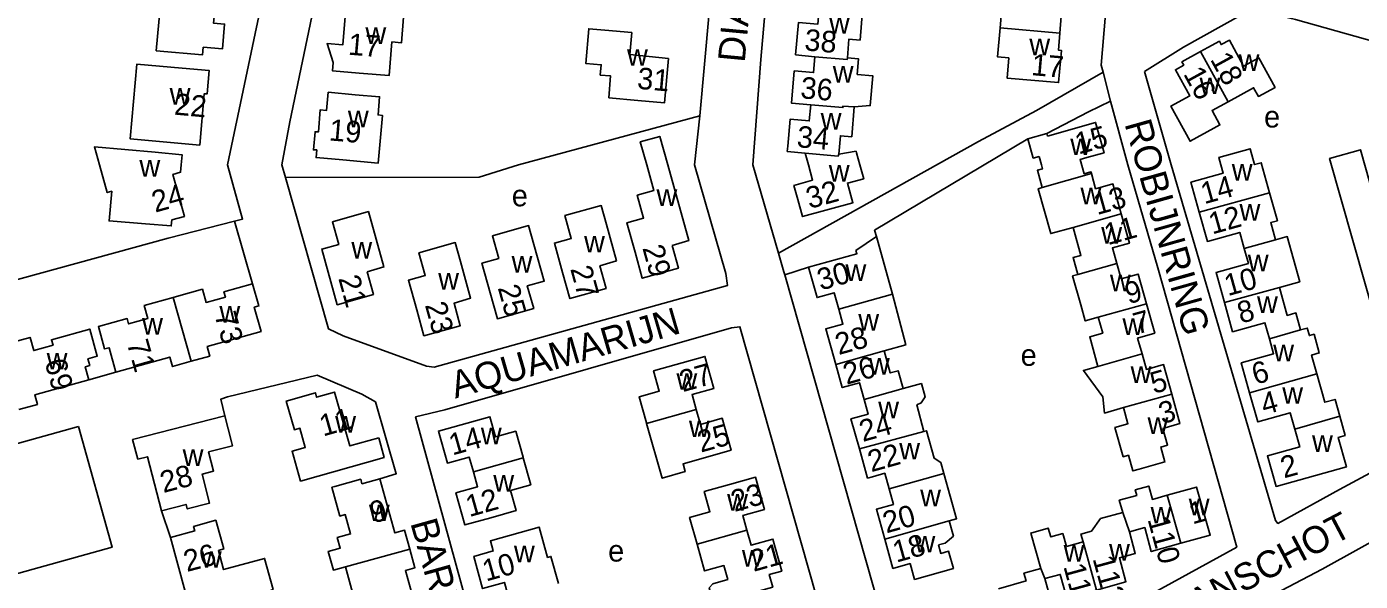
# Model space of a CAD drawing. Extents: x 159441 to 162086, y 388175 to 389787.
# Drawn here: x 159843.1 to 160090.5, y 388422.7 to 388525.7 of the extents above; entities that cross this region are included whole.
import ezdxf

# ---------------------------------------------------------------- set-up
doc = ezdxf.new("R2010")
doc.units = 0
for name, color, linetype in [('BLT_Basislijn', 7, 'Continuous'), ('BLT_Bebouwing', 7, 'Continuous'), ('BLT_Centroide', 7, 'Continuous'), ('BLT_Huisnummer', 7, 'Continuous'), ('BLT_Huisnummer_ tussenligend', 7, 'Continuous'), ('BLT_Onderverdeling_panden', 7, 'Continuous'), ('BLT_Straatnaam', 7, 'Continuous')]:
    doc.layers.add(name, color=color, linetype=linetype)

msp = doc.modelspace()

# ---------------------------------------------------------------- linework, layer by layer
at = {"layer": 'BLT_Basislijn'}
for p, q in [((160042.82, 388517.23), (160044.18, 388511.83)), ((159884.99, 388477.96), (159881.64, 388489.55)), ((159988.12, 388481.03), (159983.72, 388479.59)), ((159859.61, 388461.57), (159854.59, 388460.15)), ((159868.09, 388435.82), (159869.73, 388430.84))]:
    msp.add_line(p, q, dxfattribs=at)
for points in [[(159891.07, 388497.69), (159890.41, 388500), (159891.9, 388508.03), (159910.92, 388599.34), (159955.29, 388634.61), (159956.63, 388635.6), (159957.4, 388635.69), (159960.58, 388634.48), (159981.08, 388624.35), (159997.24, 388603.77)], [(159881.64, 388489.55), (159883.13, 388489.92), (159880.31, 388500), (159901.75, 388601.71), (159904.27, 388615.04)], [(159997.24, 388603.77), (159976.03, 388587.11), (159974.89, 388585.92), (159967.94, 388509.11)], [(160007.91, 388598.99), (159987, 388582.82), (159984.23, 388575.97), (159979.27, 388519.56), (159977.78, 388500), (159982.53, 388483.63)], [(160042.82, 388517.23), (160042.45, 388518.56), (160045.07, 388549.89), (160045.32, 388550.52), (160046.02, 388551.08)], [(160069.29, 388528.74), (160068.45, 388527.87), (160057.7, 388521.87), (160050.49, 388517.35)], [(160119.41, 388515.48), (160078.46, 388526.99), (160070.12, 388528.98), (160069.29, 388528.74)], [(160042.82, 388517.23), (160030.41, 388510.14), (160019.67, 388504.39), (159982.53, 388483.63)], [(160100.2, 388447.07), (160086.64, 388439.75), (160075.23, 388433.46), (160074.75, 388434.01), (160055.42, 388500), (160050.49, 388517.35)], [(160044.18, 388511.83), (160047.34, 388500), (160052.91, 388480.91), (160067.59, 388429.07), (160008.55, 388396.67), (160007.63, 388396.55), (160006.91, 388397.91), (159983.72, 388479.59)], [(160044.18, 388511.83), (160040.05, 388509.89), (160032.33, 388505.82)], [(159891.07, 388497.69), (159926.99, 388497.75), (159934.29, 388500), (159967.94, 388509.11)], [(159967.94, 388509.11), (159966.98, 388500), (159972.81, 388479.85), (159973.11, 388477.66), (159918.64, 388462.48), (159917.27, 388462.67), (159901.76, 388468.27), (159899.06, 388469.61), (159891.07, 388497.69)], [(160028.82, 388504.83), (160000.39, 388487.88), (160000.71, 388486.74)], [(160105.46, 388450.09), (160090.56, 388502.82), (160084.8, 388501.19), (160100.2, 388447.07)], [(159824.86, 388474.25), (159869.34, 388486.43), (159881.64, 388489.55)], [(159982.53, 388483.63), (159983.56, 388480.15), (159983.72, 388479.59)], [(159934.85, 388382.82), (159925.9, 388414.21), (159915.23, 388453.23), (159920.65, 388454.53), (159973.85, 388469.77), (159975.39, 388469.98), (159995.27, 388399.83)], [(159908.61, 388441.76), (159911.63, 388442.69), (159907.81, 388456.01), (159905.27, 388457.45), (159896.95, 388460.98), (159880.33, 388456.97), (159879.06, 388456.51), (159879.84, 388453.47)], [(160073.38, 388419.71), (160083.44, 388425.01), (160135.09, 388453.64), (160136.7, 388454.22), (160149.05, 388411.9), (160149.19, 388410.5), (160082.23, 388391.17), (160081.75, 388391.93), (160078.89, 388400.97)], [(159852.68, 388451.49), (159858.93, 388429.04), (159832.88, 388421.82), (159829.18, 388423.91), (159824.59, 388440.25), (159826.87, 388444.28), (159852.68, 388451.49)]]:
    msp.add_lwpolyline(points, dxfattribs=at)
at = {"layer": 'BLT_Bebouwing'}
for p, q in [((160032.33, 388505.82), (160028.82, 388504.83)), ((160032.45, 388505.38), (160032.33, 388505.82))]:
    msp.add_line(p, q, dxfattribs=at)
for points in [[(159876.25, 388533.66), (159862.92, 388534.88), (159862.46, 388529.7), (159867.84, 388529.2), (159867.1, 388521.21), (159875.66, 388520.42), (159875.82, 388521.85), (159879.38, 388521.56), (159879.79, 388526.14), (159877.73, 388526.32), (159877.89, 388528.12), (159878.65, 388528.05), (159878.74, 388529.05), (159880.84, 388528.87), (159881.23, 388533.21), (159876.25, 388533.66)], [(160023.66, 388525.43), (160024.12, 388530.66), (160026.22, 388530.48), (160026.52, 388533.95)], [(160032.53, 388533.85), (160036.12, 388533.54), (160035.6, 388527.56), (160035.03, 388527.61), (160034.76, 388524.47)], [(159907.22, 388527.89), (159902.24, 388528.29), (159901.71, 388522.28), (159898.8, 388522.54), (159899.91, 388519.02), (159899.8, 388517.48), (159904.78, 388517.06), (159910.3, 388516.6), (159910.82, 388522.85), (159912.61, 388522.7), (159913, 388527.43), (159907.22, 388527.89)], [(159989.31, 388520.09), (159985.73, 388520.46), (159986.25, 388526.43), (159989.83, 388526.12), (159990.08, 388529.04)], [(159995.33, 388519.91), (159995.6, 388523.35), (159997.69, 388523.17), (159998.17, 388528.7), (159996.13, 388528.88)], [(159951.05, 388512.46), (159956.43, 388511.99), (159961.41, 388511.56), (159962.12, 388519.76), (159954.95, 388520.52), (159955.33, 388524.59), (159950.35, 388525.02), (159947.34, 388525.28), (159946.78, 388518.86), (159949.66, 388518.61), (159949.49, 388516.7), (159951.4, 388516.53), (159951.05, 388512.46)], [(160034.76, 388524.47), (160034.48, 388521.32), (160035.05, 388521.27), (160034.53, 388515.29), (160024.96, 388516.12), (160025.29, 388519.88), (160023.2, 388520.06), (160023.66, 388525.43)], [(160060.88, 388521.05), (160062.22, 388521.79), (160064.35, 388522.96), (160064.68, 388522.34), (160066.21, 388523.18), (160068.85, 388518.34), (160071.69, 388519.89), (160074.69, 388514.41), (160071.6, 388512.72), (160070.71, 388514.34), (160065.99, 388511.75)], [(159988.53, 388511.14), (159984.95, 388511.49), (159985.47, 388517.47), (159989.05, 388517.16), (159989.31, 388520.09)], [(159997.13, 388516.78), (159997.39, 388519.73), (159995.33, 388519.91)], [(160065.99, 388511.75), (160062.99, 388510.12), (160064.45, 388507.45), (160063.3, 388506.82), (160058.92, 388504.42), (160055.36, 388510.92), (160058.87, 388512.83), (160056.21, 388517.69), (160057.74, 388518.53), (160057.4, 388519.14), (160060.88, 388521.05)], [(159875.18, 388503.67), (159876.02, 388513.23), (159876.52, 388513.19), (159876.92, 388517.56), (159871.94, 388518), (159863.52, 388518.74), (159862.28, 388504.83), (159875.18, 388503.67)], [(159996.61, 388510.77), (159999.59, 388511.02), (160000.07, 388516.52), (159997.13, 388516.78)], [(159903.99, 388513.05), (159908.55, 388512.66), (159908.26, 388509.28), (159909.05, 388509.21), (159908.28, 388500.35), (159901.74, 388500.93), (159896.76, 388501.38), (159896.87, 388502.79), (159896.27, 388502.81), (159896.56, 388506.18), (159897.18, 388506.13), (159897.53, 388510.24), (159898.72, 388510.13), (159899.01, 388513.49), (159903.99, 388513.05)], [(159987.51, 388502.17), (159984.17, 388502.51), (159984.26, 388503.52), (159984.69, 388508.5), (159988.27, 388508.19), (159988.53, 388511.14)], [(159993.74, 388501.98), (159994.04, 388505.42), (159996.13, 388505.24), (159996.61, 388510.77)], [(160032.45, 388505.38), (160041.4, 388507.89), (160042.97, 388502.27), (160039.78, 388501.37), (160038.52, 388501.02), (160039.26, 388498.38), (160040.52, 388498.74), (160040.6, 388498.44)], [(159962.85, 388485.08), (159965.94, 388485.98), (159962.02, 388500), (159960.53, 388505.32), (159956.9, 388504.3), (159958.1, 388500), (159959.43, 388495.25), (159956.35, 388494.39), (159957.53, 388490.14), (159954.4, 388489.27), (159955.93, 388483.8), (159957.27, 388478.98), (159963.99, 388480.87), (159962.85, 388485.08)], [(160028.82, 388504.83), (160029.82, 388501.27), (160030.91, 388501.58)], [(159866.92, 388502.36), (159871.9, 388501.91), (159871.74, 388500), (159871.62, 388498.66), (159870.15, 388498.26), (159872.32, 388490.46), (159870, 388489.81), (159869.89, 388488.7), (159865.08, 388489.09), (159858.35, 388489.62), (159858.85, 388495.12), (159858.01, 388494.89), (159856.58, 388500), (159855.64, 388503.38), (159866.92, 388502.36)], [(159993.74, 388501.98), (159996.96, 388502.55), (159997.04, 388502.28), (159997.67, 388500), (159998.37, 388497.46), (159995.35, 388496.63), (159996.35, 388493), (159987.02, 388490.42), (159986.14, 388493.61), (159985.42, 388496.22), (159988.89, 388497.18), (159988.11, 388500), (159987.51, 388502.17)], [(160060.62, 388491.24), (160059.07, 388496.8), (160065.06, 388498.47), (160064.64, 388500), (160064.25, 388501.4), (160070.07, 388503.02), (160070.88, 388500.09), (160072.12, 388500.43), (160073.68, 388494.81)], [(160031.49, 388495.81), (160030.58, 388499.04), (160031.54, 388499.31), (160031.35, 388500), (160030.91, 388501.58)], [(160040.6, 388498.44), (160041.4, 388495.59), (160044.59, 388496.48), (160046.15, 388490.93)], [(160037.2, 388488.42), (160033.06, 388487.26), (160030.72, 388495.59), (160031.49, 388495.81)], [(160073.68, 388494.81), (160075.12, 388489.64), (160073.88, 388489.3), (160074.77, 388486.11)], [(159950.64, 388488.98), (159952.49, 388482.21), (159949.41, 388481.26), (159950.56, 388477.08), (159943.84, 388475.22), (159942.5, 388480.04), (159940.99, 388485.51), (159944.11, 388486.38), (159942.93, 388490.61), (159949.67, 388492.48), (159950.64, 388488.98)], [(159906.24, 388480.19), (159907.4, 388475.98), (159900.69, 388474.07), (159897.82, 388484.39), (159900.95, 388485.22), (159899.78, 388489.47), (159906.46, 388491.34), (159909.35, 388481.09), (159906.24, 388480.19)], [(160046.15, 388490.93), (160047.67, 388485.5), (160044.51, 388484.6), (160045.32, 388481.73)], [(160068.96, 388484.48), (160068.12, 388487.48), (160062.13, 388485.81), (160060.62, 388491.24)], [(159937.18, 388485.23), (159939.1, 388478.44), (159935.95, 388477.56), (159937.13, 388473.34), (159930.4, 388471.46), (159929.06, 388476.27), (159927.52, 388481.76), (159930.65, 388482.63), (159929.47, 388486.87), (159936.2, 388488.75), (159937.18, 388485.23)], [(160037.2, 388488.42), (160038.66, 388483.22), (160037.2, 388482.81), (160038.08, 388479.67)], [(159923.57, 388482.06), (159925.43, 388475.3), (159922.35, 388474.35), (159923.5, 388470.16), (159916.77, 388468.3), (159915.43, 388473.12), (159913.89, 388478.62), (159917.02, 388479.5), (159915.84, 388483.72), (159922.58, 388485.6), (159923.57, 388482.06)], [(159988.12, 388481.03), (159997.09, 388483.54), (159996.93, 388484.1), (160000.71, 388486.74)], [(160000.71, 388486.74), (160003.7, 388476.01)], [(160074.77, 388486.11), (160076.94, 388486.72), (160079.27, 388478.34), (160075.51, 388477.29)], [(160065.3, 388474.45), (160063.74, 388480.04), (160069.73, 388481.71), (160068.96, 388484.48)], [(159993.74, 388473.23), (159992.89, 388476.28), (159989.71, 388475.39), (159988.12, 388481.03)], [(160045.32, 388481.73), (160046.15, 388478.84), (160049.31, 388479.74), (160050.83, 388474.25)], [(159884.99, 388477.96), (159879.66, 388476.48), (159879.93, 388475.49), (159876.34, 388474.49), (159875.66, 388476.94), (159870.85, 388475.6), (159870.22, 388475.43)], [(159884.99, 388477.96), (159886.14, 388473.83), (159885.3, 388473.6), (159886.56, 388469.07), (159876.55, 388466.29), (159877.04, 388464.54), (159873.58, 388463.56)], [(160038.08, 388479.67), (160037.12, 388479.4), (160038.62, 388474.05), (160039.46, 388471.05), (160041.87, 388471.75)], [(160075.51, 388477.29), (160076.96, 388472.09), (160078.55, 388472.54), (160079.43, 388469.38)], [(159859.61, 388461.57), (159858.36, 388466.09), (159857.52, 388465.86), (159856.37, 388470), (159861.71, 388471.48), (159861.98, 388470.5), (159865.55, 388471.49), (159864.87, 388473.94), (159870.22, 388475.43)], [(160003.7, 388476.01), (160006.16, 388466.61), (160002.14, 388465.51)], [(159993.17, 388462.99), (159991.32, 388469.59), (159994.52, 388470.48), (159993.74, 388473.23)], [(160050.83, 388474.25), (160052.36, 388468.76), (160049.18, 388467.87), (160050, 388464.95)], [(160073.64, 388467.74), (160072.8, 388470.73), (160066.8, 388469.06), (160065.3, 388474.45)], [(160041.87, 388471.75), (160042.71, 388468.76), (160040.29, 388468.08), (160041.82, 388462.62)], [(159838.23, 388466.48), (159843.68, 388468.01), (159844.37, 388465.56), (159847.95, 388466.56), (159847.66, 388467.57), (159854.76, 388469.55), (159856.16, 388464.53), (159854.41, 388464.04), (159854.76, 388462.79), (159853.92, 388462.55), (159854.59, 388460.15)], [(160069.97, 388457.73), (160068.42, 388463.29), (160074.41, 388464.96), (160073.64, 388467.74)], [(160079.43, 388469.38), (160080.67, 388469.73), (160081.07, 388468.33), (160081.93, 388468.57), (160082.9, 388465.11), (160081.45, 388464.71), (160082.45, 388461.22)], [(160002.14, 388465.51), (160003.29, 388461.4), (160004.74, 388461.81), (160005.68, 388458.49)], [(160050, 388464.95), (160050.81, 388462.07), (160053.99, 388462.96), (160055.52, 388457.49)], [(159873.58, 388463.56), (159870.12, 388462.58), (159869.62, 388464.36), (159859.61, 388461.57)], [(159967.3, 388454.62), (159966.52, 388457.38), (159970.56, 388458.51), (159968.9, 388464.46), (159959.37, 388461.78), (159960.43, 388458.03), (159956.68, 388456.97), (159958.04, 388452.16), (159958.07, 388452.04)], [(159998.44, 388456.47), (159997.57, 388459.57), (159994.38, 388458.68), (159993.17, 388462.99)], [(160041.82, 388462.62), (160039.12, 388461.87), (160042.72, 388456.95), (160043.07, 388453.95), (160046.55, 388454.99)], [(159854.59, 388460.15), (159844.57, 388457.34), (159845.06, 388455.57), (159841.6, 388454.59)], [(160082.45, 388461.22), (160083.91, 388455.97), (160085.83, 388456.5), (160086.7, 388453.38)], [(159908.37, 388449.35), (159909.38, 388445.72), (159893.88, 388441.33), (159892.3, 388446.88), (159894.76, 388447.58), (159893.75, 388451.14), (159892.74, 388450.85), (159891.23, 388456.19), (159896.62, 388457.72), (159896.85, 388456.89), (159900.2, 388457.84), (159903.02, 388447.87), (159908.37, 388449.35)], [(160005.68, 388458.49), (160009.07, 388459.43), (160009.76, 388456.98), (160009.03, 388455.85), (160008.23, 388455.49), (160009.55, 388450.53)], [(160046.55, 388454.99), (160047.4, 388451.98), (160044.98, 388451.3), (160046.51, 388445.86), (160047.47, 388446.13), (160048.29, 388443.21), (160049.45, 388443.54), (160054.26, 388444.89), (160053.49, 388447.63), (160054.76, 388447.99), (160053.88, 388451.12), (160057.04, 388452.01), (160055.52, 388457.49)], [(160078.34, 388450.99), (160077.49, 388454), (160071.48, 388452.31), (160069.97, 388457.73)], [(159997.56, 388447.32), (159996, 388452.88), (159999.19, 388453.77), (159998.44, 388456.47)], [(159879.84, 388453.47), (159862.72, 388449.03), (159863.71, 388445.4), (159865.49, 388445.86), (159868.09, 388435.82)], [(159868.09, 388435.82), (159872.63, 388437), (159872.85, 388436.17), (159876.99, 388437.24), (159875.6, 388442.61), (159877.74, 388443.16), (159876.81, 388446.74), (159881.28, 388447.9), (159881.09, 388448.63), (159879.84, 388453.47)], [(159935.2, 388445.65), (159935.16, 388445.78), (159933.81, 388450.59), (159930.05, 388449.54), (159929.01, 388453.28), (159919.46, 388450.61), (159921.13, 388444.66), (159925.16, 388445.8), (159925.94, 388443.03)], [(159958.07, 388452.04), (159960.99, 388441.87), (159965.25, 388443.08), (159964.84, 388444.53), (159973.77, 388447.05), (159972.11, 388453), (159968.07, 388451.86), (159967.3, 388454.62)], [(160086.7, 388453.38), (160087.69, 388449.81), (160086.39, 388449.45), (160087.92, 388443.96), (160074.87, 388440.33), (160073.28, 388445.99), (160079.27, 388447.67), (160078.34, 388450.99)], [(160009.55, 388450.53), (160009.99, 388450.66), (160011.41, 388445.57), (160012.69, 388444.76), (160013.26, 388442.73)], [(159925.94, 388443.03), (159926.72, 388440.27), (159922.69, 388439.13), (159924.36, 388433.18), (159929.18, 388434.53), (159933.9, 388435.85), (159932.85, 388439.6), (159936.6, 388440.65), (159935.2, 388445.65)], [(160003.08, 388439.88), (160002.27, 388442.78), (160000, 388442.15), (159999.08, 388441.89), (159997.56, 388447.32)], [(160013.26, 388442.73), (160015.61, 388434.34), (160014.23, 388433.95)], [(159902.19, 388425.42), (159899.96, 388424.8), (159898.99, 388428.29), (159901.23, 388428.9), (159900.69, 388430.84), (159903.16, 388431.52), (159902.17, 388435.1), (159901.17, 388434.82), (159899.68, 388440.2), (159900.21, 388440.35), (159905.03, 388441.68), (159905.26, 388440.84), (159908.61, 388441.76)], [(159914.14, 388428.71), (159913.17, 388432.19), (159911.39, 388431.7), (159908.61, 388441.76)], [(159976.69, 388432.19), (159975.91, 388434.95), (159979.95, 388436.08), (159978.29, 388442.03), (159973.48, 388440.68), (159968.77, 388439.37), (159969.82, 388435.64), (159966.06, 388434.59), (159967.46, 388429.6)], [(160046.42, 388435.51), (160045.79, 388437.77), (160049.02, 388438.67), (160048.74, 388439.69), (160051.25, 388440.39), (160051.93, 388437.93), (160054.69, 388438.7)], [(160054.69, 388438.7), (160060.13, 388440.23), (160062.66, 388431.32), (160057.18, 388429.79)], [(160002.26, 388430.58), (160000.71, 388436.1), (160003.89, 388436.99), (160003.08, 388439.88)], [(160039.07, 388430.03), (160038.66, 388431.5), (160040.61, 388432.05), (160042.32, 388434.36), (160046.42, 388435.51)], [(159869.73, 388430.84), (159874.25, 388432.09), (159874.02, 388432.93), (159878.15, 388434.07), (159879.63, 388428.73), (159878.63, 388428.45), (159879.61, 388424.89), (159887.19, 388426.98), (159888.79, 388421.2), (159888.35, 388421.08)], [(159932.48, 388419.76), (159931.7, 388422.52), (159927.66, 388421.39), (159926, 388427.35), (159929.63, 388428.37), (159929.1, 388430.24), (159938.14, 388432.79), (159939.72, 388427.17), (159940.34, 388427.34), (159941.74, 388422.35)], [(160014.23, 388433.95), (160015.02, 388431.1), (160013.48, 388429.83), (160012.23, 388429.48)], [(159871.81, 388416.44), (159870.72, 388420.36), (159872.49, 388420.85), (159869.73, 388430.84)], [(159967.46, 388429.6), (159968.84, 388424.66), (159972.42, 388425.66), (159973.13, 388423.06), (159970.34, 388422.28), (159969.72, 388421.51), (159970.52, 388418.59), (159981.5, 388421.66), (159980.85, 388423.98), (159983.17, 388424.62), (159981.51, 388430.56), (159977.46, 388429.42), (159976.69, 388432.19)], [(160012.23, 388429.49), (160012.67, 388427.91), (160014.1, 388428.31), (160015, 388425.09), (160012.6, 388424.42), (160007.79, 388423.07), (160006.97, 388426.01), (160003.79, 388425.12), (160002.26, 388430.58)], [(160031.21, 388425.11), (160029.37, 388431.69), (160032.6, 388432.6), (160033.06, 388430.96), (160035.29, 388431.58), (160035.97, 388429.16), (160039.07, 388430.03)], [(160047.65, 388431.92), (160048.75, 388427.89), (160045.8, 388427.08), (160047.01, 388422.64), (160041.53, 388421.11)], [(160057.18, 388429.79), (160051.71, 388428.26), (160050.5, 388432.7), (160047.65, 388431.92)], [(159916.11, 388414.69), (159913.33, 388424.74), (159915.11, 388425.24), (159914.14, 388428.71)], [(159916.11, 388414.69), (159911.56, 388413.43), (159911.79, 388412.59), (159907.62, 388411.43), (159906.14, 388416.82), (159907.14, 388417.09), (159906.15, 388420.67), (159903.69, 388419.99), (159902.19, 388425.42)], [(160023.39, 388421.36), (160028.49, 388422.79), (160028.09, 388424.23), (160031.21, 388425.11)], [(160032, 388423.24), (160033.09, 388419.21), (160030.15, 388418.41), (160031.36, 388413.97), (160025.87, 388412.45)], [(160041.53, 388421.11), (160036.05, 388419.58), (160034.84, 388424.02), (160032, 388423.24)]]:
    msp.add_lwpolyline(points, dxfattribs=at)
at = {"layer": 'BLT_Onderverdeling_panden'}
for p, q in [((160034.76, 388524.47), (160023.66, 388525.43)), ((160060.88, 388521.05), (160065.99, 388511.75)), ((160031.49, 388495.81), (160040.6, 388498.44)), ((160073.68, 388494.81), (160060.62, 388491.24)), ((160037.2, 388488.42), (160046.15, 388490.93)), ((160074.77, 388486.11), (160068.96, 388484.48)), ((160045.32, 388481.73), (160038.08, 388479.67)), ((160075.51, 388477.29), (160065.3, 388474.45)), ((159873.58, 388463.56), (159870.22, 388475.43)), ((159993.74, 388473.23), (160003.7, 388476.01)), ((160050.83, 388474.25), (160041.87, 388471.75)), ((160079.43, 388469.38), (160073.64, 388467.74)), ((160002.14, 388465.51), (159993.17, 388462.99)), ((160050, 388464.95), (160041.82, 388462.62)), ((160082.45, 388461.22), (160069.97, 388457.73)), ((159998.44, 388456.47), (160005.68, 388458.49)), ((160055.52, 388457.49), (160046.55, 388454.99)), ((159967.3, 388454.62), (159958.07, 388452.04)), ((160086.7, 388453.38), (160078.34, 388450.99)), ((160009.55, 388450.53), (159997.56, 388447.32)), ((159925.94, 388443.03), (159935.2, 388445.65)), ((160003.08, 388439.88), (160013.26, 388442.73)), ((160057.18, 388429.79), (160054.69, 388438.7)), ((160046.42, 388435.51), (160047.65, 388431.92)), ((160014.23, 388433.95), (160002.26, 388430.58)), ((159976.69, 388432.19), (159967.46, 388429.6)), ((159914.14, 388428.71), (159902.19, 388425.42)), ((160041.53, 388421.11), (160039.07, 388430.03)), ((160031.21, 388425.11), (160032, 388423.24))]:
    msp.add_line(p, q, dxfattribs=at)
for points in [[(159989.31, 388520.09), (159995.3, 388519.61), (159995.33, 388519.91)], [(159988.53, 388511.14), (159994.5, 388510.67), (159994.52, 388510.95), (159996.61, 388510.77)], [(159987.51, 388502.17), (159993.62, 388501.65), (159993.74, 388501.98)]]:
    msp.add_lwpolyline(points, dxfattribs=at)

# ---------------------------------------------------------------- texts
at = {"layer": 'BLT_Centroide'}
for s, p in [('w', (159991.93, 388524.38)), ('w', (159905.91, 388522.48)), ('w', (160029.09, 388520.38)), ('w', (159954.45, 388518.41)), ('w', (160067.93, 388517.47)), ('w', (159992.62, 388515.31)), ('w', (160060.67, 388513.16)), ('w', (159869.59, 388511.19)), ('w', (159902.66, 388507)), ('w', (159990.38, 388506.56)), ('e', (160072.65, 388506.96)), ('w', (160036.69, 388501.84)), ('w', (159863.98, 388497.83)), ('w', (159991.89, 388496.92)), ('w', (160066.65, 388497.12)), ('e', (159933.07, 388492.33)), ('w', (159959.91, 388492.42)), ('w', (160038.59, 388492.69)), ('w', (160068.09, 388489.66)), ('w', (160042.44, 388485.39)), ('w', (159903.3, 388482.64)), ('w', (159946.48, 388483.77)), ('w', (159933.03, 388480.03)), ('w', (160069.63, 388480.28)), ('w', (159919.41, 388476.88)), ('w', (159994.98, 388478.47)), ('w', (160044.05, 388476.56)), ('w', (160071.34, 388472.53)), ('w', (159878.82, 388470.75)), ('w', (159997.36, 388469.28)), ('w', (159864.48, 388468.5)), ('w', (160046.38, 388468.44)), ('w', (159846.77, 388462.06)), ('e', (160027.49, 388462.72)), ('w', (160074.34, 388463.56)), ('w', (159999.33, 388461.09)), ('w', (160047.89, 388459.53)), ('w', (159963.62, 388458.28)), ('w', (160076.02, 388455.69)), ('w', (160001.05, 388453)), ('w', (159900.3, 388450.31)), ('w', (159965.93, 388449.5)), ('w', (160051.02, 388450.09)), ('w', (159927.33, 388448.16)), ('w', (160004.95, 388445.34)), ('w', (160081.55, 388446.75)), ('w', (159872, 388444.14)), ('w', (159929.64, 388439.38)), ('w', (159973.02, 388435.86)), ('w', (160008.84, 388436.66)), ('w', (160058.67, 388435)), ('w', (159906.56, 388433.91)), ('w', (160051.59, 388433.47)), ('w', (160007.79, 388428.09)), ('w', (159875.39, 388425.25)), ('w', (159933.47, 388426.28)), ('e', (159950.95, 388426.39)), ('w', (159975.77, 388425.47)), ('w', (160035.45, 388426.39)), ('w', (160043.89, 388426.58))]:
    msp.add_text(s, height=4, dxfattribs=at).set_placement(p)
at = {"layer": 'BLT_Huisnummer'}
for s, rotation, p in [('17', 355.2002, (159902.6, 388520.49)), ('17', 355.0222, (160029.36, 388516.69)), ('18', 298.6796, (160062.57, 388519.62)), ('31', 355.0414, (159956.22, 388514.16)), ('16', 298.6796, (160057.58, 388516.93)), ('36', 355.0323, (159986.52, 388512.41)), ('22', 354.8763, (159870.33, 388509.36)), ('19', 355.2002, (159899.06, 388504.57)), ('15', 15.631, (160038.22, 388501.93)), ('32', 15.4747, (159988.31, 388491.82)), ('14', 15.5549, (160061.55, 388492.7)), ('24', 15.6404, (159866.9, 388491.14)), ('11', 15.631, (160043.65, 388485.09)), ('29', 285.5479, (159957.27, 388484.61)), ('27', 285.5479, (159943.89, 388480.74)), ('30', 15.631, (159990.38, 388476.68)), ('10', 15.5549, (160065.92, 388475.64)), ('21', 285.5479, (159900.85, 388478.98)), ('25', 285.5479, (159930.44, 388477.22)), ('73', 285.6432, (159877.88, 388472.17)), ('23', 285.5479, (159916.92, 388474.03)), ('7', 15.631, (160049.03, 388468.52)), ('71', 285.6432, (159861.61, 388466.98)), ('69', 285.6432, (159846.35, 388463.47)), ('27', 15.6467, (159964.81, 388457.83)), ('26', 15.631, (159995.17, 388459.19)), ('6', 15.5549, (160071.02, 388459.19)), ('3', 15.631, (160053.73, 388451.88)), ('11', 15.7848, (159898.05, 388449.59)), ('14', 15.6436, (159922.05, 388446.07)), ('25', 15.6467, (159968.15, 388446.6)), ('22', 15.631, (159999.76, 388442.96)), ('2', 15.5549, (160076.34, 388441.82)), ('28', 14.7835, (159868.42, 388439.1)), ('23', 15.6467, (159974.38, 388435.58)), ('9', 15.7848, (159907.39, 388433.45)), ('12', 15.6436, (159925.18, 388434.63)), ('1', 15.631, (160059.36, 388433.27)), ('110', 285.2944, (160051, 388434.25)), ('18', 15.631, (160004.4, 388426.17)), ('26', 14.7835, (159872.78, 388424.44)), ('10', 15.6436, (159928.28, 388422.67)), ('21', 15.6467, (159977.93, 388424.47)), ('114', 285.2944, (160035.39, 388425.5))]:
    msp.add_text(s, height=4, rotation=rotation, dxfattribs=at).set_placement(p)
at = {"layer": 'BLT_Huisnummer_ tussenligend'}
for s, rotation, p in [('38', 355.0323, (159987.26, 388521.29)), ('34', 354.9641, (159985.84, 388503.32)), ('13', 15.631, (160041.66, 388490.69)), ('12', 15.5549, (160063.02, 388487.09)), ('9', 15.631, (160047.48, 388474.14)), ('8', 15.5549, (160068.33, 388470.54)), ('28', 15.631, (159993.72, 388464.71)), ('5', 15.631, (160052.17, 388457.5)), ('4', 15.5549, (160072.69, 388453.58)), ('24', 15.631, (159998.19, 388448.58)), ('20', 15.631, (160002.56, 388431.61)), ('112', 285.2944, (160040.81, 388426.95))]:
    msp.add_text(s, height=4, rotation=rotation, dxfattribs=at).set_placement(p)
at = {"layer": 'BLT_Straatnaam'}
for s, rotation, p in [('DIAMANTRING', 84.6488, (159976.28, 388518.91)), ('ROBIJNRING', 285.7504, (160046.72, 388507.67)), ('AQUAMARIJN', 16.196, (159922.59, 388456.63)), ('AANSCHOT', 27.723, (160056.42, 388414.1)), ('BARNSTEEN', 285.6489, (159914.21, 388433.59))]:
    msp.add_text(s, height=5, rotation=rotation, dxfattribs=at).set_placement(p)

doc.saveas('drawing.dxf')
